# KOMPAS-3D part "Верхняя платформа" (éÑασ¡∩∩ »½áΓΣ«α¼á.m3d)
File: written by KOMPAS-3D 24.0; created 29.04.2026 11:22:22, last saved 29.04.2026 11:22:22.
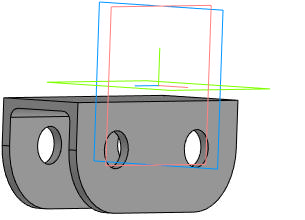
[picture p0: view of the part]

Document properties: Автор: USG_411; Полное имя файла: C:\Users\USG_411\Desktop\ИА-2904_411-12\Верхняя платформа.m3d

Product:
- Part/product: Верхняя платформа
    Масса: 0.160905

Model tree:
1. Эскиз:1
2. Элемент выдавливания:1
     Расстояние 2 = 30
3. Эскиз:2  (with: Ребро.Элемент выдавливания:1)
4. Элемент выдавливания:2
     Расстояние 1 = 40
